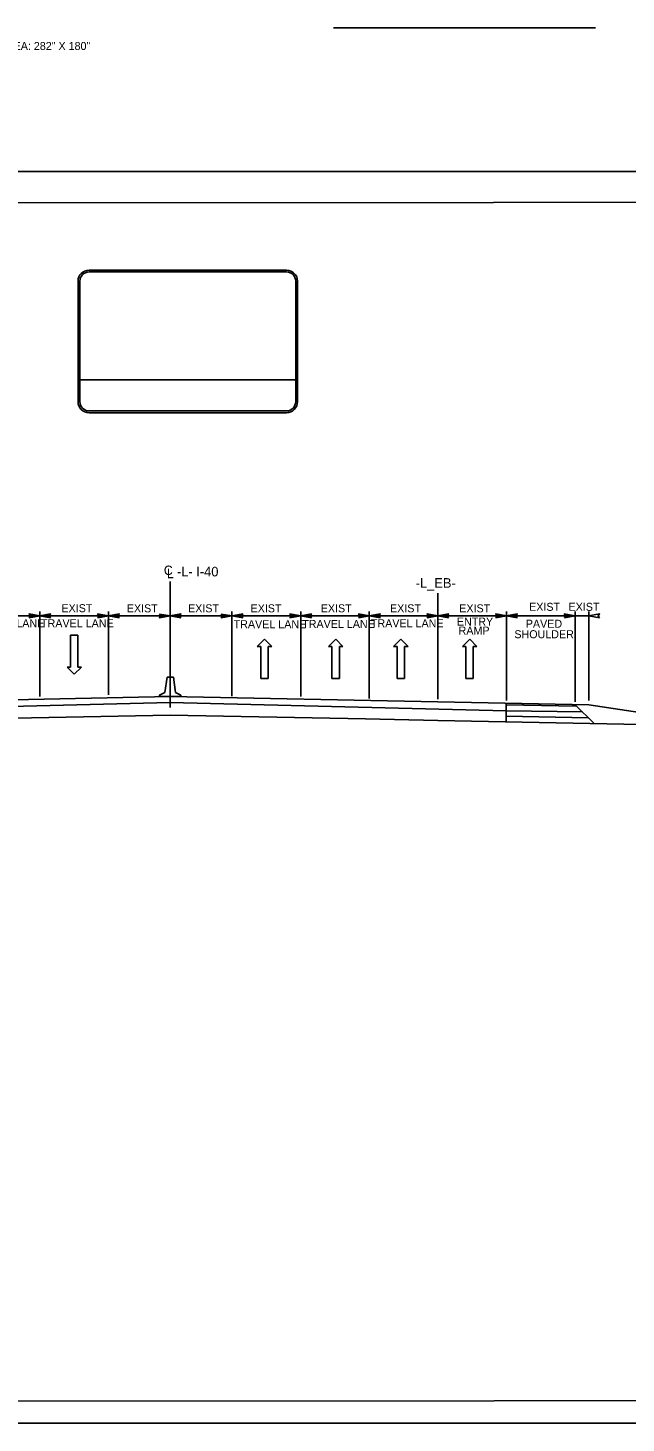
# Model space of a CAD drawing. Extents: x 1726582 to 1728895, y 538986 to 541550.
# Drawn here: x 1727337 to 1727860, y 538986 to 540208 of the extents above; entities that cross this region are included whole.
import ezdxf

# ---------------------------------------------------------------- set-up
doc = ezdxf.new("R2010")
doc.units = 0
for name, color, linetype in [('Default', 7, 'Continuous'), ('GSDIMS', 7, 'Continuous'), ('GSOUTLINE', 7, 'Continuous'), ('GSProposed', 7, 'Continuous'), ('GSRemove', 7, 'Continuous'), ('GSReplace', 7, 'Continuous'), ('Sheet Plot Border Outside CELL', 7, 'Continuous')]:
    doc.layers.add(name, color=color, linetype=linetype)

msp = doc.modelspace()

# ---------------------------------------------------------------- linework, layer by layer
at = {"layer": 'Default'}
for p, q in [((1727603.9, 540207.6), (1727833.1, 540207.6)), ((1727695.3, 539619.9), (1727695.3, 539712.8)), ((1727347, 539622.3), (1727347, 539696.5)), ((1727407, 539623.5), (1727407, 539696.5)), ((1727515.1, 539622.5), (1727515.1, 539696.5)), ((1727575.3, 539622.3), (1727575.3, 539696.7)), ((1727635.3, 539620.5), (1727635.3, 539696.6)), ((1727695.3, 539619.9), (1727695.3, 539696.6)), ((1727755.3, 539618.7), (1727755.3, 539696.5)), ((1727815.4, 539618.7), (1727815.4, 539696.5)), ((1727815.4, 539617.5), (1727815.4, 539696.5)), ((1727827.4, 539618.7), (1727827.4, 539696.5)), ((1727286.9, 539692.8), (1727347, 539692.8)), ((1727347, 539692.8), (1727407, 539692.8)), ((1727407, 539692.8), (1727461, 539692.8)), ((1727461, 539692.8), (1727515.2, 539692.8)), ((1727515.2, 539692.8), (1727575.3, 539692.8)), ((1727575.3, 539692.8), (1727635.3, 539692.8)), ((1727635.3, 539692.8), (1727695.4, 539692.8)), ((1727695.4, 539692.8), (1727755.4, 539692.8)), ((1727755.4, 539692.8), (1727815.5, 539692.8)), ((1727755.4, 539692.8), (1727815.5, 539692.8)), ((1727815.5, 539692.8), (1727827.4, 539692.8)), ((1727373.8, 539647.9), (1727373.8, 539675.9)), ((1727373.8, 539675.9), (1727380.4, 539675.9)), ((1727380.4, 539675.9), (1727380.4, 539647.9)), ((1727543.7, 539672.3), (1727537.3, 539666)), ((1727549.9, 539666), (1727543.7, 539672.3)), ((1727606, 539672.3), (1727599.6, 539666)), ((1727612.2, 539666), (1727606, 539672.3)), ((1727663, 539672.3), (1727656.6, 539666)), ((1727669.2, 539666), (1727663, 539672.3)), ((1727723.1, 539672.3), (1727716.7, 539666)), ((1727729.3, 539666), (1727723.1, 539672.3)), ((1727537.3, 539666), (1727540.3, 539666)), ((1727540.3, 539666), (1727540.3, 539638)), ((1727546.9, 539638), (1727546.9, 539666)), ((1727546.9, 539666), (1727549.9, 539666)), ((1727599.6, 539666), (1727602.6, 539666)), ((1727602.6, 539666), (1727602.6, 539638)), ((1727609.2, 539638), (1727609.2, 539666)), ((1727609.2, 539666), (1727612.2, 539666)), ((1727656.6, 539666), (1727659.6, 539666)), ((1727659.6, 539666), (1727659.6, 539638)), ((1727666.2, 539638), (1727666.2, 539666)), ((1727666.2, 539666), (1727669.2, 539666)), ((1727716.7, 539666), (1727719.7, 539666)), ((1727719.7, 539666), (1727719.7, 539638)), ((1727726.3, 539638), (1727726.3, 539666)), ((1727726.3, 539666), (1727729.3, 539666)), ((1727377.2, 539641.6), (1727370.8, 539647.9)), ((1727370.8, 539647.9), (1727373.8, 539647.9)), ((1727383.4, 539647.9), (1727377.2, 539641.6)), ((1727380.4, 539647.9), (1727383.4, 539647.9)), ((1727540.3, 539638), (1727546.9, 539638)), ((1727602.6, 539638), (1727609.2, 539638)), ((1727659.6, 539638), (1727666.2, 539638)), ((1727719.7, 539638), (1727726.3, 539638))]:
    msp.add_line(p, q, dxfattribs=at)
for points in [[(1727337.6, 539691.2), (1727347, 539692.8), (1727337.6, 539694.5), (1727338.8, 539692.8)], [(1727356.4, 539691.2), (1727347, 539692.8), (1727356.4, 539694.5), (1727355.2, 539692.8)], [(1727397.7, 539691.2), (1727407, 539692.8), (1727397.6, 539694.5), (1727398.8, 539692.8)], [(1727416.4, 539691.2), (1727407, 539692.8), (1727416.5, 539694.5), (1727415.3, 539692.8)], [(1727451.7, 539694.4), (1727461, 539692.8), (1727451.6, 539691.1), (1727452.8, 539692.8)], [(1727470.4, 539691.2), (1727461, 539692.8), (1727470.5, 539694.5), (1727469.3, 539692.8)], [(1727505.8, 539694.4), (1727515.1, 539692.8), (1727505.7, 539691.1), (1727506.9, 539692.8)], [(1727524.5, 539691.2), (1727515.1, 539692.8), (1727524.6, 539694.5), (1727523.4, 539692.8)], [(1727565.9, 539691.2), (1727575.3, 539692.8), (1727565.9, 539694.5), (1727567.1, 539692.8)], [(1727584.7, 539691.2), (1727575.3, 539692.8), (1727584.7, 539694.5), (1727583.5, 539692.8)], [(1727626, 539691.2), (1727635.3, 539692.8), (1727625.9, 539694.5), (1727627.1, 539692.8)], [(1727644.7, 539691.2), (1727635.3, 539692.8), (1727644.8, 539694.5), (1727643.6, 539692.8)], [(1727685.9, 539691.2), (1727695.3, 539692.8), (1727685.8, 539694.5), (1727687, 539692.8)], [(1727704.7, 539691.2), (1727695.3, 539692.8), (1727704.7, 539694.5), (1727703.5, 539692.8)], [(1727745.9, 539691.2), (1727755.3, 539692.8), (1727745.9, 539694.5), (1727747.1, 539692.8)], [(1727764.7, 539691.2), (1727755.3, 539692.8), (1727764.8, 539694.5), (1727763.6, 539692.8)], [(1727806, 539691.2), (1727815.4, 539692.8), (1727805.9, 539694.5), (1727807.1, 539692.8)], [(1727836.8, 539691.2), (1727827.4, 539692.8), (1727836.8, 539694.5), (1727835.6, 539692.8)]]:
    msp.add_lwpolyline(points, close=True, dxfattribs=at)
at = {"layer": 'GSDIMS'}
msp.add_lwpolyline([(1728243.5, 540054.9), (1726744.7, 540054.1), (1726745.3, 539005), (1728244.1, 539005.8)], close=True, dxfattribs=at)
at = {"layer": 'GSOUTLINE'}
for p, q in [((1727562.9, 539995.5), (1727390.1, 539995.5)), ((1727562.9, 539993.9), (1727390.1, 539993.9)), ((1727380.5, 539985.9), (1727380.5, 539880.3)), ((1727382.1, 539985.9), (1727382.1, 539880.3)), ((1727570.9, 539880.3), (1727570.9, 539985.9)), ((1727572.5, 539880.3), (1727572.5, 539985.9)), ((1727380.5, 539880.3), (1727380.5, 539899.5)), ((1727380.5, 539899.5), (1727382.1, 539899.5)), ((1727572.5, 539899.5), (1727380.5, 539899.5)), ((1727380.5, 539899.5), (1727380.5, 539880.3)), ((1727382.1, 539899.5), (1727382.1, 539897.9)), ((1727382.1, 539897.9), (1727382.1, 539880.3)), ((1727570.9, 539897.9), (1727570.9, 539899.5)), ((1727570.9, 539899.5), (1727572.5, 539899.5)), ((1727570.9, 539880.3), (1727570.9, 539897.9)), ((1727572.5, 539899.5), (1727572.5, 539880.3)), ((1727572.5, 539880.3), (1727572.5, 539899.5)), ((1727390.1, 539872.3), (1727562.9, 539872.3)), ((1727390.1, 539872.3), (1727562.9, 539872.3)), ((1727390.1, 539870.7), (1727562.9, 539870.7)), ((1727562.9, 539870.7), (1727390.1, 539870.7)), ((1727390.1, 539870.7), (1727562.9, 539870.7))]:
    msp.add_line(p, q, dxfattribs=at)
for centre, radius, start, end in [((1727390.1, 539985.9), 9.6, 90, 180), ((1727390.1, 539985.9), 8, 90, 180), ((1727562.9, 539985.9), 9.6, 0, 90), ((1727562.9, 539985.9), 8, 0, 90), ((1727390.1, 539880.3), 9.6, 180, 270), ((1727390.1, 539880.3), 9.6, 180, 270), ((1727390.1, 539880.3), 9.6, 180, 270), ((1727390.1, 539880.3), 8, 180, 270), ((1727390.1, 539880.3), 8, 180, 270), ((1727562.9, 539880.3), 9.6, 270, 0), ((1727562.9, 539880.3), 8, 270, 0), ((1727562.9, 539880.3), 9.6, 270, 0), ((1727562.9, 539880.3), 8, 270, 0), ((1727562.9, 539880.3), 9.6, 270, 0)]:
    msp.add_arc(centre, radius, start, end, dxfattribs=at)
at = {"layer": 'GSRemove'}
msp.add_line((1727461, 539612.7), (1727461, 539722.8), dxfattribs=at)
at = {"layer": 'GSReplace'}
for p, q in [((1727456.5, 539625.7), (1727458.4, 539639.2)), ((1727458.4, 539639.2), (1727461.1, 539639.2)), ((1727463.9, 539639.2), (1727461.1, 539639.2)), ((1727465.8, 539625.7), (1727463.9, 539639.2)), ((1727226.8, 539617.4), (1727461, 539622.1)), ((1727695.3, 539617.4), (1727461, 539622.1)), ((1727226.8, 539611.2), (1727461, 539617)), ((1727755.1, 539609.7), (1727461, 539617)), ((1727827.4, 539614.8), (1727695.3, 539617.4)), ((1727755.1, 539600), (1727755.1, 539616.2)), ((1727816.6, 539613.8), (1727755.1, 539615)), ((1727821.7, 539608.7), (1727755.1, 539609.7)), ((1727815.4, 539615), (1727831.9, 539598.5)), ((1727827.4, 539614.8), (1727951.4, 539596.1)), ((1727226.8, 539601.2), (1727461, 539605.9)), ((1727632, 539602.5), (1727461, 539605.9)), ((1727695.3, 539601.2), (1727632, 539602.5)), ((1727958.9, 539595.9), (1727695.3, 539601.2)), ((1727826.8, 539603.6), (1727755.1, 539605))]:
    msp.add_line(p, q, dxfattribs=at)
for points in [[(1727465.7, 539622.2), (1727451.7, 539622.2), (1727451.7, 539623.3), (1727456.5, 539625.7)], [(1727456.6, 539622.2), (1727470.5, 539622.2), (1727470.5, 539623.3), (1727465.8, 539625.7)]]:
    msp.add_lwpolyline(points, dxfattribs=at)
at = {"layer": 'Sheet Plot Border Outside CELL'}
msp.add_lwpolyline([(1728264.8, 540081.9), (1726581.9, 540081.9), (1726581.9, 538986), (1728264.8, 538986)], close=True, dxfattribs=at)

# ---------------------------------------------------------------- texts
at = {"layer": 'GSProposed'}
for s, height, p in [('WINDLOAD AREA: 282" X 180"', 7.005, (1727258, 540188.3)), ('EXIST', 7.01, (1727365.9, 539696)), ('EXIST', 7.01, (1727423.1, 539695.9)), ('EXIST', 7.01, (1727476.7, 539695.9)), ('EXIST', 7.01, (1727531.4, 539695.9)), ('EXIST', 7.01, (1727592.8, 539695.9)), ('EXIST', 7.01, (1727653.4, 539695.9)), ('EXIST', 7.01, (1727714, 539695.9)), ('EXIST', 7.01, (1727775.1, 539697.2)), ('EXIST', 7.01, (1727809.6, 539697.2)), ('TRAVEL LANE', 7.005, (1727287.4, 539682.8)), ('TRAVEL LANE', 7.005, (1727348.1, 539682.8)), ('TRAVEL LANE', 7.005, (1727516.6, 539682)), ('TRAVEL LANE', 7.005, (1727576.6, 539682.2)), ('TRAVEL LANE', 7.005, (1727636.7, 539682.8)), ('ENTRY', 7.01, (1727711.9, 539684.3)), ('RAMP', 7.01, (1727713.4, 539676.4)), ('PAVED', 7.01, (1727772.2, 539682.4)), ('SHOULDER', 7.01, (1727762.2, 539673.2))]:
    msp.add_text(s, height=height, dxfattribs=at).set_placement(p)
at = {"layer": 'GSRemove'}
for s, height, rotation, p in [('C', 8.2, 0.0443, (1727455.5, 539728.6)), ('L', 8.21, 359.9912, (1727458.2, 539725.8)), ('-L- I-40', 8.42, 359.9417, (1727467, 539727.4))]:
    msp.add_text(s, height=height, rotation=rotation, dxfattribs=at).set_placement(p)
msp.add_text('-L_EB-', height=8.42, dxfattribs=at).set_placement((1727675.9, 539717.4))

doc.saveas('drawing.dxf')
